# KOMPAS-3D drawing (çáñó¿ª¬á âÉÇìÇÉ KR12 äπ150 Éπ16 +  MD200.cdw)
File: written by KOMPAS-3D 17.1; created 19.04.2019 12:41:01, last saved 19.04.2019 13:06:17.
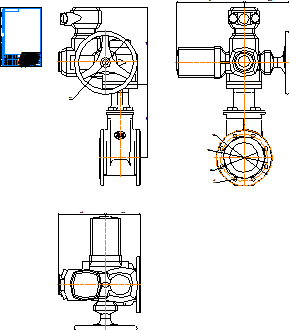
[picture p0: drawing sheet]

Sheet 1: A4, portrait

Title block, sheet 1: name: Задвижка ГРАНАР KR12 Ду150 Ру16 + / MD200; material: Внимание! Данный продукт является объектом авторского права ООО «Торговый Дом АДЛ». / Запрещается изменение, копирование, распространение / (в том числе путем копирования на другие сайты и ресурсы в Интернете) / или любое иное использование информации и объектов без предварительного / согласия правообладателя (ООО «Торговый Дом АДЛ»).; mass: 214,37; sheets: 1; organisation: ООО "Торговый дом АДЛ"; sheet format: A4; stored path: \\adlc.lan\data\АДЛ_ПКД\3D-модели\ADL production\Клиновые задвижки серии KR ГРАНАР\Клиновые задвижки KR12 с эл.приводами Смартгир\KOMPAS 2D\Задвижка ГРАНАР KR12 Ду150 Ру16 +  MD200.cdw

Views: Проекционный вид 3
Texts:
  user
Dimensions and other numbers on the sheet: 241,19; 178,81; 1:1; 1; 214,37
